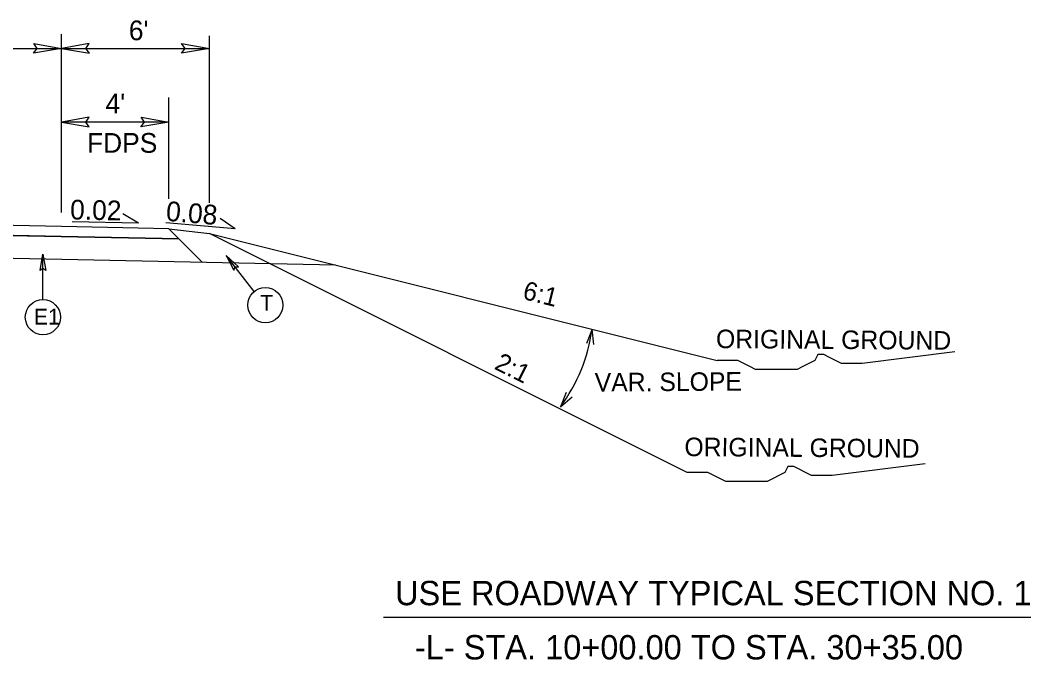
# Model space of a CAD drawing. Extents: x 2111095 to 2115970, y 670428 to 672393.
# Drawn here: x 2114021.3 to 2114436.6, y 671602.4 to 671865 of the extents above; entities that cross this region are included whole.
import ezdxf

# ---------------------------------------------------------------- set-up
doc = ezdxf.new("R2010")
doc.units = 0
for name, color, linetype in [('Old_Level_1', 7, 'Continuous'), ('Old_Level_11', 7, 'Continuous'), ('Old_Level_20', 7, 'Continuous'), ('Old_Level_3', 7, 'Continuous'), ('Prop Leader Line Medium', 7, 'Continuous'), ('Prop Shade Medium', 7, 'Continuous'), ('Typical Pavement Slope CELL', 7, 'Continuous'), ('Typical Pavement Slope Information CELL', 7, 'Continuous'), ('Typical Shoulder Slope CELL', 7, 'Continuous'), ('Typical Shoulder Slope Information CELL', 7, 'Continuous'), ('Typical Terminator CELL', 7, 'Continuous'), ('Typical Text Grade Point CELL', 7, 'Continuous')]:
    doc.layers.add(name, color=color, linetype=linetype)

msp = doc.modelspace()

# ---------------------------------------------------------------- linework, layer by layer
at = {"layer": 'Old_Level_1'}
for p, q in [((2114038.22, 671780.32), (2113892.45, 671783.22)), ((2114099.02, 671777.43), (2114307.66, 671725.29)), ((2114295.37, 671679.28), (2114099.02, 671777.43))]:
    msp.add_line(p, q, dxfattribs=at)
for points in [[(2114405.42, 671728.84), (2114367.29, 671724.08), (2114364.86, 671724.08), (2114361.2, 671724.08), (2114358.77, 671724.08), (2114356.33, 671725.3), (2114353.9, 671726.52), (2114351.47, 671727.74), (2114349.04, 671727.74), (2114347.81, 671725.3), (2114345.38, 671724.08), (2114342.95, 671722.86), (2114340.51, 671721.65), (2114338.08, 671721.65), (2114335.65, 671721.65), (2114333.21, 671721.65), (2114330.78, 671721.65), (2114328.35, 671721.65), (2114325.91, 671721.65), (2114323.48, 671721.65), (2114321.05, 671722.86), (2114318.61, 671724.08), (2114316.18, 671725.29), (2114312.53, 671725.29), (2114310.09, 671725.29), (2114307.66, 671725.29)], [(2114393.12, 671682.82), (2114355, 671678.07), (2114352.56, 671678.07), (2114348.91, 671678.07), (2114346.47, 671678.07), (2114344.04, 671679.28), (2114341.61, 671680.5), (2114339.17, 671681.72), (2114336.74, 671681.72), (2114335.52, 671679.28), (2114333.09, 671678.07), (2114330.65, 671676.85), (2114328.22, 671675.63), (2114325.79, 671675.63), (2114323.35, 671675.63), (2114320.92, 671675.63), (2114318.49, 671675.63), (2114316.05, 671675.63), (2114313.62, 671675.63), (2114311.19, 671675.63), (2114308.75, 671676.84), (2114306.32, 671678.07), (2114303.89, 671679.28), (2114300.23, 671679.28), (2114297.8, 671679.28), (2114295.37, 671679.28)]]:
    msp.add_lwpolyline(points, dxfattribs=at)
at = {"layer": 'Old_Level_11'}
for p, q in [((2114030.61, 671750.31), (2114030.61, 671769)), ((2114117.43, 671753.63), (2114105.95, 671768.39))]:
    msp.add_line(p, q, dxfattribs=at)
for points in [[(2114029.46, 671762.31), (2114030.61, 671769), (2114031.8, 671762.28), (2114030.61, 671763.13)], [(2114110.97, 671763.82), (2114105.95, 671768.39), (2114109.14, 671762.35), (2114109.56, 671763.76)]]:
    msp.add_lwpolyline(points, close=True, dxfattribs=at)
for points in [[(2114257, 671731.91), (2114256.28, 671738.13), (2114253.98, 671732.3)], [(2114245.6, 671712.12), (2114243.29, 671706.3), (2114248.07, 671710.34)]]:
    msp.add_lwpolyline(points, dxfattribs=at)
for centre in [(2114121.99, 671748.03), (2114030.61, 671743.09)]:
    msp.add_circle(centre, 7.22, dxfattribs=at)
msp.add_arc((2114187.34, 671747.68), 69.59, 323.5075, 352.1105, dxfattribs=at)
at = {"layer": 'Old_Level_3'}
msp.add_line((2114170.64, 671619.83), (2114436.57, 671619.83), dxfattribs=at)
at = {"layer": 'Prop Leader Line Medium'}
for p, q in [((2114038.22, 671786.02), (2114038.22, 671859.32)), ((2114099.02, 671789.98), (2114099.02, 671858.68)), ((2113941.05, 671853.48), (2114038.25, 671853.48)), ((2114038.25, 671853.48), (2114099.02, 671853.48)), ((2114082.36, 671791.75), (2114082.36, 671833.27)), ((2114082.36, 671823.22), (2114038.22, 671823.22))]:
    msp.add_line(p, q, dxfattribs=at)
at = {"layer": 'Prop Shade Medium'}
for p, q in [((2114038.22, 671780.32), (2113892.45, 671783.22)), ((2114082.36, 671779.43), (2114038.22, 671780.32)), ((2114086.49, 671775.3), (2114082.36, 671779.43)), ((2114038.14, 671776.27), (2114086.49, 671775.3))]:
    msp.add_line(p, q, dxfattribs=at)
msp.add_lwpolyline([(2113892.45, 671779.17), (2113989.78, 671777.23), (2114038.14, 671776.27)], dxfattribs=at)
at = {"layer": 'Typical Pavement Slope CELL'}
for p, q in [((2114038.14, 671776.27), (2113892.37, 671779.17)), ((2114082.36, 671779.43), (2114038.22, 671780.32)), ((2114096.22, 671765.57), (2114082.36, 671779.43)), ((2114086.49, 671775.3), (2114038.14, 671776.27)), ((2114084.5, 671765.81), (2113989.78, 671767.7)), ((2114150.83, 671764.48), (2114084.5, 671765.81))]:
    msp.add_line(p, q, dxfattribs=at)
at = {"layer": 'Typical Pavement Slope Information CELL'}
for p, q in [((2114069.83, 671781.7), (2114063.49, 671785.54)), ((2114069.83, 671781.7), (2114042.7, 671782.24)), ((2114109.56, 671779.39), (2114081.14, 671781.78)), ((2114109.56, 671779.39), (2114103.48, 671783.62))]:
    msp.add_line(p, q, dxfattribs=at)
at = {"layer": 'Typical Shoulder Slope CELL'}
msp.add_line((2114082.36, 671779.43), (2114099.02, 671777.43), dxfattribs=at)
at = {"layer": 'Typical Terminator CELL'}
for points in [[(2114026.86, 671855.44), (2114038.25, 671853.48), (2114026.8, 671851.45), (2114028.25, 671853.48)], [(2114049.64, 671855.44), (2114038.25, 671853.48), (2114049.7, 671851.45), (2114048.25, 671853.48)], [(2114087.63, 671855.44), (2114099.02, 671853.48), (2114087.57, 671851.45), (2114089.02, 671853.48)], [(2114049.61, 671825.18), (2114038.22, 671823.22), (2114049.67, 671821.2), (2114048.21, 671823.22)], [(2114070.97, 671825.18), (2114082.36, 671823.22), (2114070.91, 671821.2), (2114072.36, 671823.22)]]:
    msp.add_lwpolyline(points, close=True, dxfattribs=at)

# ---------------------------------------------------------------- texts
at = {"layer": 'Old_Level_1'}
for s, height, rotation, p in [('6:1', 7.607, 345.9691, (2114227.38, 671750.68)), ('ORIGINAL GROUND', 7.6069, 359.6033, (2114307.19, 671730.39)), ('2:1', 7.607, 333.4393, (2114215.73, 671722)), ('VAR. SLOPE', 7.607, 0.3967, (2114257.39, 671712.53)), ('ORIGINAL GROUND', 7.6069, 359.6033, (2114294.21, 671686.05))]:
    msp.add_text(s, height=height, rotation=rotation, dxfattribs=at).set_placement(p)
at = {"layer": 'Old_Level_20'}
for s, height, p in [('T', 6.46, (2114119.9, 671745.72)), ('E1', 6.461, (2114026.96, 671740.08))]:
    msp.add_text(s, height=height, dxfattribs=at).set_placement(p)
at = {"layer": 'Prop Leader Line Medium'}
for s, p in [("6'", (2114065.92, 671856.81)), ("4'", (2114056.35, 671826.81)), ('FDPS', (2114048.74, 671810.61))]:
    msp.add_text(s, height=8.1, rotation=360, dxfattribs=at).set_placement(p)
at = {"layer": 'Typical Pavement Slope Information CELL'}
msp.add_text('0.02', height=8.1, rotation=358.8543, dxfattribs=at).set_placement((2114041.74, 671783.24))
at = {"layer": 'Typical Shoulder Slope Information CELL'}
msp.add_text('0.08', height=8.1, rotation=355.2385, dxfattribs=at).set_placement((2114080.97, 671782.7))
at = {"layer": 'Typical Text Grade Point CELL'}
for s, p in [('USE ROADWAY TYPICAL SECTION NO. 1', (2114175.32, 671624.8)), ('-L- STA. 10+00.00 TO STA. 30+35.00', (2114183.49, 671602.54))]:
    msp.add_text(s, height=10, rotation=360, dxfattribs=at).set_placement(p)

doc.saveas('drawing.dxf')
